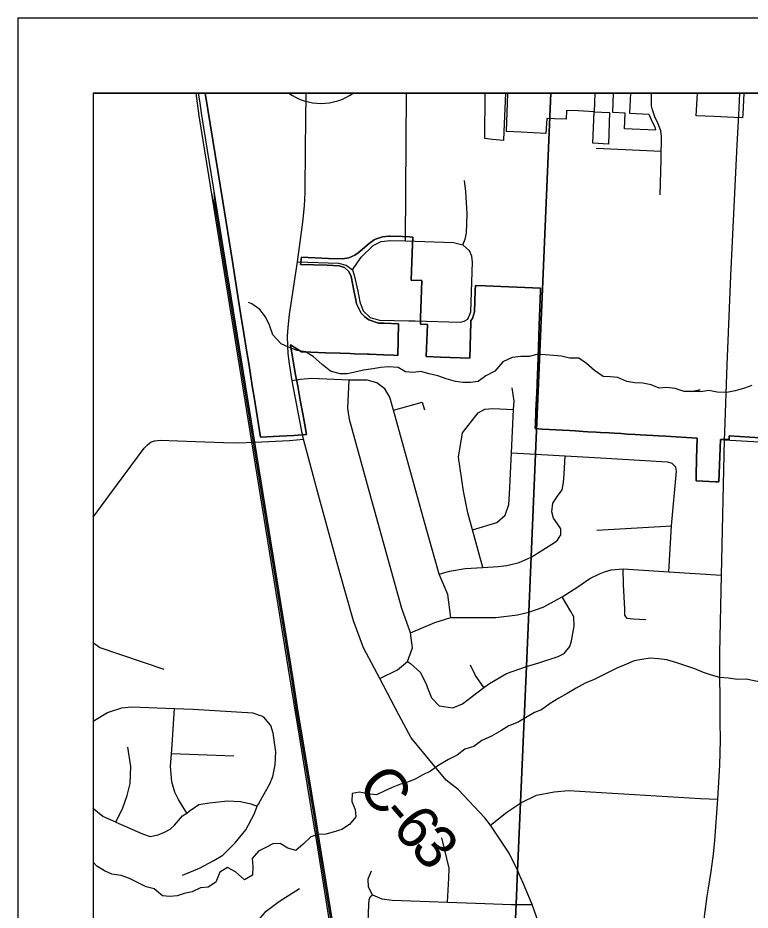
# Model space of a CAD drawing. Extents: x 0 to 34, y 0 to 22.
# Drawn here: x 3.318 to 4.29, y 19.012 to 20.196 of the extents above; entities that cross this region are included whole.
import ezdxf

# ---------------------------------------------------------------- set-up
doc = ezdxf.new("R2010")
doc.units = 0
for name, color, linetype in [('GM_X_City_Street', 7, 'Continuous'), ('GM_X_Corporation', 7, 'Continuous'), ('GM_X_County_Road', 7, 'Continuous'), ('GM_X_County_Road_Text', 7, 'Continuous'), ('GM_X_Minor_River', 7, 'Continuous'), ('GM_X_Rail_Line', 7, 'Continuous'), ('GM_X_Township_Road', 7, 'Continuous'), ('GM_X_US_Shield', 7, 'Continuous'), ('SH_Data', 7, 'Continuous')]:
    doc.layers.add(name, color=color, linetype=linetype)

msp = doc.modelspace()

# ---------------------------------------------------------------- linework, layer by layer
at = {"layer": 'GM_X_City_Street'}
for p, q in [((3.8325, 19.9006), (3.8338, 20.0965)), ((4.0852, 20.0237), (4.1714, 20.0196)), ((4.0864, 19.5166), (4.1851, 19.5225)), ((3.522, 19.2203), (3.6048, 19.2173))]:
    msp.add_line(p, q, dxfattribs=at)
for points in [[(4.1703, 19.9615), (4.1716, 20.0086), (4.1714, 20.0196), (4.1718, 20.0297), (4.1719, 20.0388), (4.171, 20.0466), (4.1675, 20.0559), (4.1631, 20.0652), (4.1599, 20.0743), (4.1587, 20.0797), (4.1586, 20.0854), (4.1589, 20.0965)], [(3.9085, 19.8953), (3.9116, 19.9028), (3.9135, 19.9106), (3.914, 19.9363), (3.9125, 19.966), (3.9105, 19.9808)], [(3.7622, 19.862), (3.7736, 19.8789), (3.7894, 19.8945), (3.8002, 19.8997), (3.8121, 19.9012), (3.8325, 19.9006)], [(3.8325, 19.9006), (3.8959, 19.8984), (3.9085, 19.8953)], [(3.9151, 19.7966), (3.9192, 19.8062), (3.9214, 19.8723), (3.9205, 19.8801), (3.9171, 19.8871), (3.9085, 19.8953)], [(3.689, 19.8729), (3.7437, 19.8708), (3.7537, 19.8681), (3.7622, 19.862), (3.7645, 19.8548), (3.769, 19.8339), (3.7718, 19.8197), (3.7764, 19.8079), (3.7854, 19.7988), (3.7977, 19.7954), (3.8367, 19.7944), (3.8453, 19.7942)], [(3.8453, 19.7942), (3.9047, 19.7927), (3.9102, 19.7938), (3.9151, 19.7966)], [(3.8927, 19.4007), (3.8886, 19.4311), (3.8771, 19.4581), (3.8575, 19.5271), (3.8166, 19.676), (3.8115, 19.6929), (3.8048, 19.7043), (3.7943, 19.7123), (3.7814, 19.7155), (3.7575, 19.7159), (3.7082, 19.718), (3.6929, 19.7167), (3.6821, 19.7148)], [(3.7985, 19.3198), (3.8218, 19.3315), (3.8351, 19.3424), (3.8417, 19.3604), (3.839, 19.3803), (3.8277, 19.4125), (3.7891, 19.5513), (3.758, 19.6635), (3.7559, 19.6786), (3.7575, 19.7159)], [(3.9214, 19.5173), (3.9534, 19.5268), (3.9648, 19.5364), (3.9696, 19.5505), (3.9704, 19.5646), (3.973, 19.6193), (3.9758, 19.6768), (3.9764, 19.688), (3.9738, 19.7055)], [(3.8166, 19.676), (3.8544, 19.6864), (3.8576, 19.6764)], [(3.9348, 19.4672), (3.9214, 19.5173), (3.915, 19.5397), (3.9092, 19.5685), (3.9028, 19.6137), (3.908, 19.6456), (3.9287, 19.6723), (3.9377, 19.6772), (3.9483, 19.6782), (3.9758, 19.6768)], [(3.4182, 19.5341), (3.4404, 19.5638), (3.4858, 19.6254), (3.4901, 19.63), (3.4949, 19.6337), (3.5001, 19.6353), (3.507, 19.636), (3.5537, 19.6342), (3.591, 19.6328), (3.6101, 19.6325), (3.6324, 19.6335), (3.6784, 19.6355), (3.697, 19.6374)], [(4.2557, 19.6365), (4.3398, 19.6317), (4.3534, 19.6299), (4.3696, 19.6265), (4.3886, 19.6206), (4.3979, 19.6165), (4.4059, 19.6161), (4.4128, 19.6192), (4.4162, 19.6234), (4.4179, 19.6348)], [(3.8771, 19.4581), (3.8906, 19.4622), (3.9115, 19.4658), (3.9348, 19.4672), (3.9551, 19.4684), (3.9666, 19.4696), (3.983, 19.4739), (3.9991, 19.4806), (4.0299, 19.5002), (4.034, 19.5035), (4.0383, 19.5103), (4.0383, 19.5184), (4.0341, 19.5252), (4.0289, 19.5324), (4.0263, 19.5408), (4.0278, 19.5523), (4.0342, 19.5619), (4.04, 19.5702), (4.042, 19.5801), (4.0427, 19.591), (4.044, 19.6151)], [(3.973, 19.6193), (4.005, 19.6174), (4.044, 19.6151), (4.0837, 19.613), (4.18, 19.6073), (4.1857, 19.6055), (4.191, 19.6003)], [(4.1819, 19.4612), (4.1851, 19.5225), (4.192, 19.595), (4.191, 19.6003)], [(3.839, 19.3803), (3.8712, 19.3943), (3.8927, 19.4007), (3.9377, 19.4008), (3.9524, 19.4008), (3.9809, 19.4041), (3.996, 19.4079), (4.0148, 19.4145), (4.0401, 19.4282), (4.0608, 19.4416), (4.0771, 19.4527), (4.0896, 19.4589), (4.0965, 19.4612), (4.1052, 19.4638), (4.1213, 19.4655), (4.1819, 19.4612), (4.2516, 19.4568)], [(4.1513, 19.3977), (4.1343, 19.3986), (4.1265, 19.3996), (4.1234, 19.4038), (4.1232, 19.4119), (4.1217, 19.4445), (4.1213, 19.4655)], [(3.8351, 19.3424), (3.8389, 19.3399), (3.8523, 19.3276), (3.8604, 19.3114), (3.8615, 19.3074), (3.8669, 19.294), (3.8769, 19.2837), (3.8951, 19.2811), (3.9079, 19.2863), (3.9363, 19.308), (3.9436, 19.3133), (3.9663, 19.3266), (3.9929, 19.3356), (4.0092, 19.3405), (4.035, 19.3492), (4.0427, 19.3529), (4.0503, 19.3621), (4.0527, 19.3696), (4.0561, 19.3892), (4.0555, 19.4017), (4.0516, 19.4087), (4.0401, 19.4282)], [(3.4182, 19.3669), (3.42, 19.3663), (3.4268, 19.3611), (3.5119, 19.3322)], [(3.9363, 19.308), (3.9254, 19.3237), (3.9187, 19.3375)], [(3.4182, 19.263), (3.4371, 19.2746), (3.4561, 19.2807), (3.469, 19.2824), (3.5261, 19.28), (3.5507, 19.279), (3.6298, 19.2741), (3.6384, 19.2713), (3.6418, 19.2701), (3.6444, 19.2686)], [(3.5422, 19.1413), (3.5315, 19.1594), (3.5263, 19.169), (3.5224, 19.1827), (3.5205, 19.2029), (3.522, 19.2203), (3.5225, 19.2252), (3.5261, 19.28)], [(3.5364, 19.0587), (3.5593, 19.0682), (3.578, 19.0781), (3.5899, 19.0854), (3.6065, 19.1018), (3.6208, 19.119), (3.6318, 19.1397), (3.6357, 19.1502), (3.6362, 19.1514), (3.6372, 19.1531), (3.6428, 19.1627), (3.6526, 19.18), (3.6566, 19.1898), (3.6595, 19.2053), (3.6606, 19.2227), (3.6569, 19.2471), (3.6537, 19.2574), (3.6444, 19.2686)], [(3.448, 19.129), (3.4574, 19.1482), (3.4634, 19.1644), (3.4671, 19.1803), (3.4679, 19.2031), (3.4642, 19.2286)], [(3.9453, 19.1251), (3.9667, 19.1424), (3.9852, 19.1549), (4.0061, 19.1648), (4.0294, 19.1694), (4.0484, 19.1711), (4.2239, 19.1606), (4.2466, 19.1597)], [(3.448, 19.129), (3.4307, 19.1369), (3.4188, 19.1466), (3.4182, 19.1476)], [(3.448, 19.129), (3.4837, 19.1136), (3.4938, 19.11), (3.5041, 19.1124), (3.5128, 19.1161), (3.5201, 19.1201), (3.5259, 19.1253), (3.5367, 19.1377), (3.5422, 19.1413), (3.5455, 19.1436), (3.5582, 19.1524), (3.5726, 19.1548), (3.5962, 19.1575), (3.6136, 19.1564), (3.6271, 19.1535), (3.6357, 19.1502)], [(3.6371, 18.9988), (3.6476, 19.0111), (3.6652, 19.0245), (3.6917, 19.0411)]]:
    msp.add_lwpolyline(points, dxfattribs=at)
at = {"layer": 'GM_X_Corporation'}
for points in [[(3.9184, 17.601), (3.9468, 18.3161), (3.9605, 18.6483), (3.9621, 18.6649), (3.9633, 18.6757), (3.9791, 19.0203), (3.9811, 19.0651), (3.9815, 19.0743), (3.985, 19.1554), (3.9927, 19.3361), (3.9958, 19.4084), (3.9989, 19.4811), (4.0048, 19.6179), (4.0253, 20.0965), (3.4182, 20.0965), (3.4182, 13.2965)], [(4.3028, 19.6393), (4.2617, 19.6416), (4.2616, 19.6371), (4.2502, 19.637), (4.2482, 19.5807), (4.2442, 19.5809), (4.2178, 19.5823), (4.2179, 19.5885), (4.2185, 19.6119), (4.2191, 19.6388), (4.2052, 19.6396), (4.1776, 19.6412), (4.1678, 19.6419), (4.1606, 19.6422), (4.1435, 19.6432), (4.1372, 19.6436), (4.1266, 19.6442), (4.1186, 19.6447), (4.1093, 19.6452), (4.1024, 19.6456), (4.091, 19.6463), (4.0854, 19.6466), (4.0744, 19.6473), (4.068, 19.6476), (4.0574, 19.6483), (4.05, 19.6487), (4.0405, 19.6493), (4.0229, 19.6503), (4.0139, 19.6508), (4.0045, 19.6514), (4.0048, 19.6578), (4.0055, 19.6738), (4.0059, 19.6848), (4.0061, 19.69), (4.0069, 19.7085), (4.0071, 19.7117), (4.0085, 19.7453), (4.0099, 19.7888), (4.0114, 19.8347), (4.0115, 19.8377), (3.9382, 19.8407), (3.9253, 19.8412), (3.925, 19.8347), (3.9241, 19.8065), (3.9211, 19.7973), (3.9189, 19.795), (3.9189, 19.7924), (3.9176, 19.7449), (3.8787, 19.7464), (3.86, 19.7472), (3.8616, 19.7895), (3.8521, 19.7898), (3.8524, 19.7988), (3.8536, 19.8347), (3.854, 19.8479), (3.8401, 19.8484), (3.8419, 19.8961), (3.8421, 19.9056), (3.8376, 19.9058), (3.828, 19.9061), (3.8119, 19.9066), (3.8101, 19.9066), (3.8019, 19.906), (3.7924, 19.9027), (3.7908, 19.9018), (3.784, 19.8971), (3.7722, 19.8867), (3.7694, 19.8845), (3.7652, 19.8816), (3.7572, 19.8782), (3.7489, 19.8766), (3.7304, 19.8773), (3.6946, 19.8787), (3.6929, 19.8692), (3.7286, 19.8681), (3.7444, 19.8676), (3.7515, 19.865), (3.7571, 19.8599), (3.7603, 19.8531), (3.7626, 19.8416), (3.764, 19.8347), (3.7665, 19.8224), (3.7676, 19.8171), (3.7734, 19.8047), (3.7784, 19.7999), (3.7819, 19.797), (3.7837, 19.7957), (3.7967, 19.7914), (3.8043, 19.7912), (3.8233, 19.7906), (3.8224, 19.7486), (3.8164, 19.7489), (3.8031, 19.7494), (3.7842, 19.7501), (3.7818, 19.7502), (3.7647, 19.7508), (3.7592, 19.751), (3.7456, 19.7515), (3.7267, 19.7521), (3.7068, 19.7528), (3.6944, 19.7533), (3.68, 19.7626), (3.6862, 19.7251), (3.6894, 19.7079), (3.6927, 19.6891), (3.6961, 19.6711), (3.6988, 19.6562), (3.7012, 19.6436), (3.6843, 19.6422), (3.6654, 19.6413), (3.64, 19.6402), (3.6361, 19.6651), (3.6315, 19.6932), (3.6291, 19.7081), (3.6268, 19.723), (3.6244, 19.7379), (3.622, 19.7528), (3.618, 19.7776), (3.6137, 19.8044), (3.611, 19.8215), (3.6082, 19.8386), (3.6027, 19.8731), (3.5899, 19.9529), (3.5668, 20.0965), (3.4182, 20.0965), (3.4182, 17.3523)], [(6.4719, 20.0965), (4.281, 20.0965), (4.2797, 20.0685), (4.2795, 20.0639), (4.2683, 20.0643), (4.2417, 20.0655), (4.218, 20.0664), (4.2196, 20.0965), (4.1307, 20.0965), (4.1295, 20.0698), (4.155, 20.0688), (4.1593, 20.0593), (4.163, 20.0517), (4.1642, 20.0474), (4.1231, 20.0491), (4.1239, 20.07), (4.1074, 20.0708), (4.1085, 20.0965), (4.0834, 20.0965), (4.0825, 20.0719), (4.1032, 20.071), (4.1015, 20.029), (4.0808, 20.03), (4.0825, 20.0719), (4.0615, 20.0729), (4.0458, 20.0736), (4.0453, 20.062), (4.03, 20.0625), (4.0198, 20.0628), (4.0185, 20.043), (4.002, 20.0438), (3.9858, 20.0446), (3.9665, 20.0456), (3.9683, 20.0965), (3.9651, 20.0965), (3.963, 20.0458), (3.9625, 20.0336), (3.9479, 20.0352), (3.9376, 20.0363), (3.9379, 20.0965), (3.5668, 20.0965), (3.5899, 19.9529), (3.6027, 19.8731), (3.6082, 19.8386), (3.611, 19.8215), (3.6137, 19.8044), (3.618, 19.7776), (3.622, 19.7528), (3.6244, 19.7379), (3.6268, 19.723), (3.6291, 19.7081), (3.6315, 19.6932), (3.6361, 19.6651), (3.64, 19.6402), (3.6654, 19.6413), (3.6843, 19.6422), (3.7012, 19.6436), (3.6988, 19.6562), (3.6961, 19.6711), (3.6927, 19.6891), (3.6894, 19.7079), (3.6862, 19.7251), (3.68, 19.7626), (3.6944, 19.7533), (3.7068, 19.7528), (3.7267, 19.7521), (3.7456, 19.7515), (3.7592, 19.751), (3.7647, 19.7508), (3.7818, 19.7502), (3.7842, 19.7501), (3.8031, 19.7494), (3.8164, 19.7489), (3.8224, 19.7486), (3.8233, 19.7906), (3.8043, 19.7912), (3.7967, 19.7914), (3.7837, 19.7957), (3.7819, 19.797), (3.7784, 19.7999), (3.7734, 19.8047), (3.7676, 19.8171), (3.7665, 19.8224), (3.764, 19.8347), (3.7626, 19.8416), (3.7603, 19.8531), (3.7571, 19.8599), (3.7515, 19.865), (3.7444, 19.8676), (3.7286, 19.8681), (3.6929, 19.8692), (3.6946, 19.8787), (3.7304, 19.8773), (3.7489, 19.8766), (3.7572, 19.8782), (3.7652, 19.8816), (3.7694, 19.8845), (3.7722, 19.8867), (3.784, 19.8971), (3.7908, 19.9018), (3.7924, 19.9027), (3.8019, 19.906), (3.8101, 19.9066), (3.8119, 19.9066), (3.828, 19.9061), (3.8376, 19.9058), (3.8421, 19.9056), (3.8419, 19.8961), (3.8401, 19.8484), (3.854, 19.8479), (3.8536, 19.8347), (3.8524, 19.7988), (3.8521, 19.7898), (3.8616, 19.7895), (3.86, 19.7472), (3.8787, 19.7464), (3.9176, 19.7449), (3.9189, 19.7924), (3.9189, 19.795), (3.9211, 19.7973), (3.9241, 19.8065), (3.925, 19.8347), (3.9253, 19.8412), (3.9382, 19.8407), (4.0115, 19.8377), (4.0114, 19.8347), (4.0099, 19.7888), (4.0085, 19.7453), (4.0071, 19.7117), (4.0069, 19.7085), (4.0061, 19.69), (4.0059, 19.6848), (4.0055, 19.6738), (4.0048, 19.6578), (4.0045, 19.6514), (4.0139, 19.6508), (4.0229, 19.6503), (4.0405, 19.6493), (4.05, 19.6487), (4.0574, 19.6483), (4.068, 19.6476), (4.0744, 19.6473), (4.0854, 19.6466), (4.091, 19.6463), (4.1024, 19.6456), (4.1093, 19.6452), (4.1186, 19.6447), (4.1266, 19.6442), (4.1372, 19.6436), (4.1435, 19.6432), (4.1606, 19.6422), (4.1678, 19.6419), (4.1776, 19.6412), (4.2052, 19.6396), (4.2191, 19.6388), (4.2185, 19.6119), (4.2179, 19.5885), (4.2178, 19.5823), (4.2442, 19.5809), (4.2482, 19.5807), (4.2502, 19.637), (4.2616, 19.6371), (4.2617, 19.6416), (4.3028, 19.6393)], [(8.9341, 20.0965), (4.0253, 20.0965), (4.0048, 19.6179), (3.9989, 19.4811), (3.9958, 19.4084), (3.9927, 19.3361), (3.985, 19.1554), (3.9815, 19.0743), (3.9811, 19.0651), (3.9791, 19.0203), (3.9633, 18.6757), (3.9621, 18.6649), (3.9605, 18.6483), (3.9468, 18.3161), (3.9995, 18.3123), (4.1878, 18.3016), (4.3213, 18.298), (4.4914, 18.2857), (4.6278, 18.2782), (4.6446, 18.2772), (4.6794, 18.2753), (5.2805, 18.2495)]]:
    msp.add_lwpolyline(points, dxfattribs=at)
msp.add_lwpolyline([(4.0808, 20.03), (4.0825, 20.0719), (4.1032, 20.071), (4.1015, 20.029)], close=True, dxfattribs=at)
at = {"layer": 'GM_X_County_Road'}
for p, q in [((3.7002, 20.059), (3.7007, 20.0965)), ((4.2744, 20.0671), (4.2759, 20.0965)), ((4.2557, 19.6365), (4.2561, 19.6466)), ((3.9888, 19.0473), (3.985, 19.0563))]:
    msp.add_line(p, q, dxfattribs=at)
for points in [[(3.695, 19.6472), (3.6943, 19.6504), (3.6821, 19.7148), (3.6787, 19.7373), (3.6768, 19.751), (3.6761, 19.7613), (3.676, 19.7739), (3.6768, 19.7857), (3.6786, 19.803), (3.689, 19.8729), (3.696, 19.9255), (3.6984, 19.947), (3.6991, 19.9646), (3.6998, 20.0247), (3.7002, 20.059)], [(4.2561, 19.6466), (4.2592, 19.736), (4.264, 19.8543), (4.2725, 20.0278), (4.2744, 20.0671)], [(3.8712, 19.2032), (3.8397, 19.2411), (3.8237, 19.2717), (3.7985, 19.3198), (3.7765, 19.3604), (3.7632, 19.3965), (3.7441, 19.465), (3.7169, 19.563), (3.697, 19.6374), (3.6957, 19.644), (3.695, 19.6472)], [(4.2343, 19.0415), (4.2379, 19.0638), (4.2409, 19.0867), (4.2429, 19.105), (4.2466, 19.1597), (4.2493, 19.205), (4.2504, 19.2378), (4.2497, 19.2629), (4.2493, 19.3536), (4.2516, 19.4568), (4.2557, 19.6365)], [(3.9809, 19.0654), (3.97, 19.0879), (3.9453, 19.1251), (3.9376, 19.1349), (3.9024, 19.1724), (3.8863, 19.185), (3.8712, 19.2032)], [(3.985, 19.0563), (3.9842, 19.0581), (3.9813, 19.0645), (3.9809, 19.0654)], [(4.0138, 18.9825), (4.0004, 19.0201), (3.9888, 19.0473)], [(4.2869, 18.3697), (4.286, 18.3715), (4.2515, 18.4352), (4.224, 18.4898), (4.2171, 18.5041), (4.2112, 18.5231), (4.2021, 18.5636), (4.201, 18.5798), (4.2016, 18.5981), (4.2027, 18.6147), (4.206, 18.6517), (4.2118, 18.803), (4.215, 18.8563), (4.2189, 18.9177), (4.2238, 18.9634), (4.2326, 19.0308), (4.2343, 19.0415)]]:
    msp.add_lwpolyline(points, dxfattribs=at)
at = {"layer": 'GM_X_Minor_River'}
for points in [[(3.909, 19.7127), (3.8988, 19.7137), (3.8863, 19.7173), (3.8754, 19.7216), (3.8636, 19.7241), (3.8527, 19.7273), (3.8432, 19.7259), (3.8326, 19.7268), (3.8228, 19.7326), (3.8099, 19.7332), (3.7997, 19.7326), (3.7891, 19.7309), (3.7769, 19.7291), (3.7674, 19.7266), (3.7552, 19.7241), (3.7458, 19.7239), (3.7329, 19.7275), (3.7217, 19.7364), (3.7101, 19.7469), (3.6999, 19.7531), (3.6886, 19.7552), (3.6772, 19.7595), (3.6675, 19.7638), (3.6562, 19.7758), (3.6522, 19.7888), (3.6467, 19.7999), (3.6393, 19.8095), (3.6287, 19.8168), (3.6242, 19.8188)], [(4.2918, 19.7086), (4.2822, 19.7049), (4.2697, 19.7017), (4.2587, 19.6992), (4.2458, 19.6998), (4.2348, 19.7018), (4.2242, 19.7001), (4.2136, 19.7006), (4.2234, 19.7028), (4.2139, 19.7006), (4.2022, 19.7008), (4.1901, 19.7048), (4.1784, 19.7061), (4.1689, 19.7051), (4.1583, 19.7094), (4.1474, 19.7115), (4.1368, 19.712), (4.1258, 19.7141), (4.1141, 19.7192), (4.1043, 19.7201), (4.0944, 19.7206), (4.0832, 19.7284), (4.0723, 19.7377), (4.0622, 19.7447), (4.05, 19.7448), (4.0395, 19.7477), (4.0289, 19.7482), (4.0175, 19.7495), (4.0065, 19.7497), (3.9966, 19.7472), (3.9852, 19.7473), (3.9739, 19.7456), (3.9616, 19.7401), (3.9509, 19.7277), (3.939, 19.7214), (3.9287, 19.714), (3.9188, 19.7126), (3.909, 19.7127)], [(4.3077, 19.3139), (4.2842, 19.3189), (4.2729, 19.3186), (4.2604, 19.3203), (4.2494, 19.3213), (4.2384, 19.3241), (4.2275, 19.3277), (4.2162, 19.3328), (4.2041, 19.3364), (4.1924, 19.3407), (4.1792, 19.3447), (4.1682, 19.346), (4.1569, 19.347), (4.1459, 19.3452), (4.1356, 19.3431), (4.1226, 19.3376), (4.1127, 19.3336), (4.102, 19.3284), (4.0826, 19.3184), (4.0708, 19.3137), (4.0589, 19.307), (4.0467, 19.3), (4.036, 19.2937), (4.0245, 19.2866), (4.013, 19.2784), (4.0035, 19.2748), (3.9936, 19.2688), (3.9817, 19.2618), (3.9695, 19.257), (3.9588, 19.2503), (3.9466, 19.2433), (3.9336, 19.2374), (3.9229, 19.2296), (3.9111, 19.226), (3.9008, 19.2181), (3.8893, 19.2122), (3.8767, 19.2048), (3.8656, 19.197), (3.8546, 19.1915), (3.845, 19.1863), (3.8351, 19.1823), (3.8256, 19.1794), (3.8149, 19.1753), (3.805, 19.1709), (3.7939, 19.1654), (3.7818, 19.1667), (3.7712, 19.1688), (3.7617, 19.167), (3.7612, 19.1568), (3.7656, 19.1461), (3.7663, 19.1362), (3.7582, 19.126), (3.7478, 19.1193), (3.7364, 19.1157), (3.7265, 19.1132), (3.7167, 19.1126), (3.7068, 19.1097), (3.6968, 19.1), (3.6868, 19.0917), (3.6762, 19.0946), (3.6661, 19.1008), (3.6566, 19.1006), (3.6471, 19.0954), (3.6375, 19.0906), (3.629, 19.0808), (3.6297, 19.0702), (3.6295, 19.0588), (3.6188, 19.0525), (3.6068, 19.0633), (3.5963, 19.0688), (3.586, 19.0628), (3.5809, 19.0496), (3.5705, 19.0429), (3.5603, 19.0419), (3.5496, 19.0368), (3.539, 19.0347), (3.5294, 19.0314), (3.52, 19.0304), (3.5101, 19.0313), (3.4992, 19.0406)], [(3.4992, 19.0406), (3.4883, 19.0434), (3.4785, 19.0481), (3.4665, 19.0544), (3.4551, 19.0583), (3.443, 19.06), (3.4329, 19.0647), (3.4231, 19.071), (3.4182, 19.076)]]:
    msp.add_lwpolyline(points, dxfattribs=at)
at = {"layer": 'GM_X_Rail_Line'}
for q in [(3.5753, 19.9634), (3.5782, 19.9696)]:
    msp.add_line((3.5813, 19.9384), q, dxfattribs=at)
for points in [[(3.963, 17.5881), (3.8713, 18.1519), (3.8453, 18.3166), (3.8337, 18.3805), (3.8241, 18.431), (3.813, 18.4972), (3.7849, 18.6679), (3.775, 18.7301), (3.7695, 18.7645), (3.7348, 18.9785), (3.7146, 19.1036), (3.7096, 19.1346), (3.699, 19.1994), (3.6905, 19.2518), (3.6863, 19.2752), (3.6796, 19.319), (3.5714, 19.9873), (3.5586, 20.0666), (3.5547, 20.0965)], [(3.9649, 17.5884), (3.8732, 18.1522), (3.8472, 18.3169), (3.8329, 18.4051), (3.8279, 18.4317), (3.8167, 18.4978), (3.7887, 18.6685), (3.7788, 18.7307), (3.7732, 18.7651), (3.7386, 18.9791), (3.7184, 19.1042), (3.7133, 19.1352), (3.7028, 19.2), (3.6942, 19.2524), (3.6901, 19.2758), (3.6833, 19.3196), (3.5752, 19.988), (3.5624, 20.0672), (3.5598, 20.0865), (3.558, 20.0965)], [(3.8066, 18.5479), (3.7868, 18.6682), (3.7769, 18.7304), (3.7714, 18.7648), (3.7367, 18.9788), (3.7165, 19.1039), (3.7115, 19.1349), (3.7009, 19.1997), (3.6923, 19.2521), (3.6882, 19.2755), (3.6814, 19.3193), (3.5813, 19.9384)]]:
    msp.add_lwpolyline(points, dxfattribs=at)
at = {"layer": 'GM_X_Township_Road'}
msp.add_line((3.982, 19.0198), (4.0004, 19.0201), dxfattribs=at)
for points in [[(3.8882, 19.023), (3.89, 19.0547), (3.8902, 19.0682), (3.8806, 19.1085)], [(3.7826, 18.9857), (3.7838, 19.0196), (3.7842, 19.0261), (3.7855, 19.03), (3.7885, 19.0329), (3.7831, 19.0428), (3.7827, 19.0541), (3.7874, 19.0644)], [(3.7885, 19.0329), (3.8012, 19.0273), (3.8148, 19.0256), (3.8393, 19.0249), (3.8882, 19.023), (3.9377, 19.0211), (3.9727, 19.02), (3.9793, 19.0198), (3.982, 19.0198)]]:
    msp.add_lwpolyline(points, dxfattribs=at)
at = {"layer": 'GM_X_US_Shield'}
msp.add_line((3.763, 20.0965), (3.6775, 20.0965), dxfattribs=at)
msp.add_arc((3.7203, 20.1574), 0.0744, 234.9518, 305.0482, dxfattribs=at)
at = {"layer": 'SH_Data'}
for p, q in [((3.3182, 20.1965), (10.3182, 20.1965)), ((3.3182, 20.1965), (3.3182, 13.1965)), ((3.4182, 20.0965), (3.4182, 13.2965)), ((3.4182, 20.0965), (10.2182, 20.0965))]:
    msp.add_line(p, q, dxfattribs=at)

# ---------------------------------------------------------------- texts
at = {"layer": 'GM_X_County_Road_Text'}
for s, rotation, p in [('C', 308.8866, (3.7665, 19.1764)), ('-', 310.5485, (3.797, 19.1387)), ('6', 311.6115, (3.8129, 19.1201)), ('3', 312.732, (3.837, 19.093))]:
    msp.add_text(s, height=0.0568, rotation=rotation, dxfattribs=at).set_placement(p)

doc.saveas('drawing.dxf')
